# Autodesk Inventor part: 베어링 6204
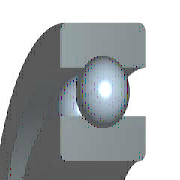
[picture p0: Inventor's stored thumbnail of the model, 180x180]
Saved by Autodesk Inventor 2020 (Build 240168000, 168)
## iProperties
IsCustomPart: 1
Created: 2012-02
Part Number: 베어링 6204
Material: 강철, 연강
Description: 단열 볼 베어링
Document SubType Name: Modeling
Standard: JIS B 1521
Designer: mdu-01
Standards Organization: JIS
Language: ko-KR
Size Designation: SKF 6204
Categories: <MemberInstance><Categories><Category DisplayName="샤프트 부품" InternalName="7f7aeb1f-a693-4053-b835-cee3144e0d98" Mnemonic="SHFT"><Category DisplayName="베어링" Inter
Density: 7.86 g/cm^3
Appearance: 강철(1)
Author: mdu-01
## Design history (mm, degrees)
node "WorkPoint1"
node "WorkAxis1"
node "WorkPlane3"
node "WorkPlane4"
node "WorkPoint2"
body "Solid1"
node "스케치1"
revolve "회전1" stored, may be unused: angle "d6" = 360 deg
revolve "회전2" stored, may be unused: angle "d10" = 360 deg
node "스케치4"
revolve "회전3" stored, may be unused: angle "d16" = 360 deg
pattern_circular "원형 배열1" dims "d17" = 66.03704 (= msp_pocet), angle "d19" = 360 deg
fillet "모깎기1" dims "d20" = 1 (= r)
sketch "스케치2"
  geometry: L1 (10, 14)-(23.5, 14); L2 (10, 0)-(10, 14); L3 (23.5, 0)-(10, 0); L4 (23.5, 14)-(23.5, 0); L5 (0, 0)-(0, 20); L6 (0, 0)-(0, 20); L7 (-7.2, 0)-(43.2, 0) reference
  constraints: 12 end point, 3 vertical, 2 horizontal, 1 collinear, 1 other
  dimensions: "d1" = 20 diameter of L1.start L5 (= Diam); "d3" = 47 diameter of L1.end L5 (= DD); "d5" = 14 distance of L2.start L1.start (= msp_mdtd2)
sketch "스케치3"
  geometry: L1 (19.18, 14)-(19.18, 10.24); L2 (14.32, 14)-(19.18, 14); L3 (14.32, 10.24)-(14.32, 14); L4 (14.32, 0)-(14.32, 3.76); L5 (19.18, 0)-(14.32, 0); L6 (19.18, 3.76)-(19.18, 0); L7 (23.5, 0)-(-23.5, 0) reference; L8 (23.5, 14)-(-23.5, 14) reference; L9 (0, -42.29)-(0, 61.29); L10 (0, 82.007)-(0, -63.007) reference; A1 r 4.05 centre (16.75, 7) between (19.18, 3.76) and (19.18, 10.24); A2 r 4.05 centre (16.75, 7) between (14.32, 10.24) and (14.32, 3.76)
  constraints: 14 end point, 4 collinear, 4 point on circle, 4 vertical, 2 centre point, 2 concentric, 2 horizontal, 2 point on line
  dimensions: "d9" = 8.1 diameter of A1 (= msp_mdtd6); "d21" = 14.32 distance between parallel lines of L9 L4 (= 0.5 x msp_d1); "d22" = 16.75 distance from line of L9 A1.centre (= 0.5 x msp_ds); "d23" = 19.18 distance between parallel lines of L9 L6 (= 0.5 x msp_dd1)
sketch "스케치5"
  geometry: L1 (16.75, 2.95)-(16.75, 11.05); L2 (19.18, 0)-(-19.18, 0) reference; L3 (16.75, 2.95)-(16.75, 11.05); A1 r 4.05 centre (16.75, 7) between (16.75, 2.95) and (16.75, 11.05); A2 r 4.05 centre (16.75, 7) between (19.18, 3.76) and (19.18, 10.24) reference
  constraints: 4 end point, 2 point on circle, 1 centre point, 1 concentric, 1 vertical
  dimensions: "d13" = 0 horizontal distance of A1.centre L1.start; "d15" = 8.1001 diameter of A1 (computed from msp_mdtd6)
other parameters: "Diam" = 20 [user parameter; used in 3 equation terms], "DD" = 47 [user parameter; used in 3 equation terms], "B" = 14 [user parameter; used in 1 equation term], "r" = 1 [user parameter; used in 1 equation term], "msp_ds" = 33.5 (= 0.5 x Diam + 0.5 x DD) [user parameter; used in 5 equation terms], "msp_d0" = 8.1 (= -0.3 x Diam + 0.3 x DD) [user parameter; used in 4 equation terms], "msp_d1" = 28.64 (= msp_ds - 0.6 x msp_d0) [user parameter; used in 1 equation term], "msp_dd1" = 38.36 (= msp_ds + 0.6 x msp_d0) [user parameter; used in 1 equation term], "msp_pom" = 50.25 (= 1.5 x msp_ds) [user parameter; used in 1 equation term], "msp_mdtd2" = 14 (= B) [user parameter; used in 3 equation terms], "msp_mdtd4" = 33.5 (= msp_ds) [user parameter], "msp_mdtd6" = 8.1 (= msp_d0) [user parameter; used in 2 equation terms], "msp_mdtd7" = 7 (= 0.5 x msp_mdtd2) [user parameter], "msp_pocet" = 66.03704 (computed from msp_d0, msp_pom) [user parameter; used in 1 equation term], "d2" = 72 (derived), "d4" = 19 (derived), "d7" = 0, "d8" = 15.6 (derived), "d11" = -14 (computed from msp_mdtd2), "d12" = 0 (derived), "d14" = 15.6001 (derived), "d26" = 0, "d27" = 0, "d28" = 0, "d29" = 0, "d30" = 0
